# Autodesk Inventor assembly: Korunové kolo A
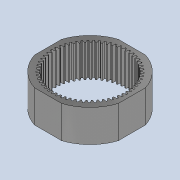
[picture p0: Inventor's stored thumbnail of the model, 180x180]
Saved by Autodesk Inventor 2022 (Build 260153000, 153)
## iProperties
Created: 2025-05
Part Number: Korunové kolo A
Document SubType Name: Assembly
Designer: jbart
Mass: 5402.18 g
Surface Area: 5816 cm^2
Volume: 5402.18 cm^3
Density: 1 g/cm^3
Author: jbart
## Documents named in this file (2)
- C:\Users\jbart\OneDrive\Dokumenty\Inventor\Převodovka navijáku\Korunové kolo 1.iam
- C:\Users\jbart\OneDrive\Dokumenty\Inventor\Převodovka navijáku\Korunové kolo 1\Design Accelerator\Čelní ozubená kola1.iam
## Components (1 placed, 1 different names)
1. Čelní ozubená kola:1 [sub-assembly]
